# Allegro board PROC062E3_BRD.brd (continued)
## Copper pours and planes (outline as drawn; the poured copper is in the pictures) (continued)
GNDUSB on L02_GND1: 7.72,135.76 7.49,135.99 7.49,137.43 7.7,137.64 8.58,137.64 9.54,138.6 8.58,139.55 7.7,139.55 7.49,139.76 7.49,142.18 7.7,142.39 8.58,142.39 9.54,143.34 8.58,144.3 7.7,144.3 7.49,144.51 7.49,146.13 7.67,146.3 11.43,146.3 11.81,145.92 11.81,143.03 11.66,142.88 10.41,142.88 10.01,142.47 10.01,139.47 10.44,139.04 11.66,139.04 11.81,138.89 11.81,135.97 11.61,135.76
GNDUSB on L03_SIG1, L04_GND2, L05_SIG2, L08_PWR3, L11_GND4: 7.72,135.76 7.49,135.99 7.49,137.43 7.7,137.64 8.58,137.64 9.54,138.6 8.58,139.55 7.7,139.55 7.49,139.76 7.49,142.18 7.7,142.39 8.58,142.39 9.54,143.34 8.58,144.3 7.7,144.3 7.49,144.51 7.49,146.13 7.67,146.3 11.13,146.3 11.33,146.1 11.33,139.62 10.9,139.19 10.9,137.36 9.3,135.76
GNDUSB on L09_GND3: 7.72,135.76 7.49,135.99 7.49,137.43 7.7,137.64 8.58,137.64 9.54,138.6 8.58,139.55 7.7,139.55 7.49,139.76 7.49,142.18 7.7,142.39 8.58,142.39 9.54,143.34 8.58,144.3 7.7,144.3 7.49,144.51 7.49,146.13 7.67,146.3 11.13,146.3 11.33,146.1 11.33,146.08 11.33,139.62 10.9,139.19 10.9,137.36 9.3,135.76
GNDUSB on L10_SIG3: 7.72,135.76 7.49,135.99 7.49,137.43 7.7,137.64 8.58,137.64 9.54,138.6 8.58,139.55 7.7,139.55 7.49,139.76 7.49,142.18 7.7,142.39 8.58,142.39 9.54,143.34 8.58,144.3 7.7,144.3 7.49,144.51 7.49,146.13 7.67,146.3 11.13,146.3 11.33,146.1 11.33,139.62 10.9,139.19 10.9,137.36 9.3,135.76
GNDUSB on L12_SIG4: 7.72,135.76 7.49,135.99 7.49,137.43 7.7,137.64 8.58,137.64 9.54,138.6 8.58,139.55 7.7,139.55 7.49,139.76 7.49,142.18 7.7,142.39 8.58,142.39 9.54,143.34 8.58,144.3 7.7,144.3 7.49,144.51 7.49,146.13 7.67,146.3 11.13,146.3 11.33,146.1 11.33,139.62 10.9,139.19 10.9,137.37 9.29,135.76
GNDUSB on L13_GND5: 7.72,135.76 7.49,135.99 7.49,137.43 7.7,137.64 8.58,137.64 9.54,138.6 8.58,139.55 7.7,139.55 7.49,139.76 7.49,142.18 7.7,142.39 8.58,142.39 9.54,143.34 8.58,144.3 7.7,144.3 7.49,144.51 7.49,146.13 7.67,146.3 11.13,146.3 11.33,146.1 11.33,139.62 10.9,139.19 10.9,137.52 9.14,135.76
VCC1V0 on BOTTOM: 132.02,169.29 136.46,169.29 136.46,163.64 145.99,163.64 145.99,169.1 149.48,169.1 149.48,158.62 132.02,158.62
VCC1V2_DDR on BOTTOM: 165.35,153.54 165.35,159.07 168.21,159.07 168.21,165.93 170.37,165.93 170.37,166.31 174.94,166.31 174.94,153.54
VCC1V8 on TOP: 43.69,74.55 43.69,68.96 45.21,68.96 45.21,74.55
VCC1V8 on TOP: 167.39,18.8 167.39,13.34 169.1,13.34 169.1,18.8
VCC1V8 on TOP: 184.66,69.98 184.66,66.17 190.25,66.17 190.25,69.98
VCC1V8 on BOTTOM: 153.67,10.29 153.67,8.38 153.29,8 153.29,4.83 154.88,4.83 154.88,7.18 154.37,7.68 154.37,10.29
VCC1V8 on BOTTOM: 34.73,58.74 34.73,63.94 36.26,63.94 36.26,65.98 39.37,65.98 39.37,58.74
VCC1V8 on BOTTOM: 152.65,33.4 152.65,35.17 153.36,35.88 153.36,38.16 154.18,38.16 154.18,33.4
VCC1V8 on L06_PWR1: 99.59,1.03 8.01,1.03 8.01,137.12 8.58,137.12 10.06,138.6 8.58,140.07 8.01,140.07 8.01,141.87 8.58,141.87 10.06,143.34 8.58,144.82 8.01,144.82 8.01,155.94 8.6,155.94 10.06,157.39 8.6,158.84 8.01,158.84 8.01,160.69 8.6,160.69 10.06,162.14 8.6,163.59 8.01,163.59 8.01,176.77 209.16,176.77 209.16,1.03 107.3,1.03 107.3,1.6 105.82,3.08 104.34,1.6 104.34,1.03 102.55,1.03 102.55,1.6 101.07,3.08 99.59,1.6 ; 9 cut-outs
VCC1V8_CLKBUFF on L08_PWR3: 65.45,103.22 65.45,91.81 78.11,91.81 78.11,103.22
VCC3V3_IO on TOP: 136.33,64.52 136.33,53.54 137.41,53.54 137.41,64.52
VCC3V3_IO on TOP: 116.97,66.04 116.97,53.59 118.55,53.59 118.55,66.04
VCC3V3_IO on TOP: 164.53,18.86 164.53,13.21 167.07,13.21 167.07,18.86
VCC3V3_IO on TOP: 47.43,122.24 47.43,120.08 68.01,120.08 68.01,122.24
VCC3V3_IO on TOP: 143.07,147.15 143.07,151.79 143.26,151.98 145.16,151.98 145.29,151.85 145.29,149.82 144.4,149.82 144.4,147.15
VCC3V3_IO on TOP: 57.4,69.02 58.61,69.02 58.61,74.42 56.01,74.42 56.01,71.63 57.4,71.63
VCC3V3_IO on BOTTOM: 137.67,6.53 139,6.53 139,8.57 138.81,8.76 138.81,10.29 137.67,10.29
VCC3V3_IO on BOTTOM: 201.99,28.12 201.99,28.89 200.6,28.89 200.03,29.46 198.37,29.46 198.37,28.26 200.13,28.26 200.26,28.12
VCC3V3_IO on BOTTOM: 180.72,65.15 180.72,63.12 180.85,62.99 180.85,61.47 180.98,61.34 182.5,61.34 182.75,61.59 182.75,64.75 182.35,65.15
VCC3V3_IO on BOTTOM: 152.4,17.91 152.4,13.21 152.21,13.21 152.21,10.67 152.65,10.22 152.65,8.95 153.35,8.95 153.35,10.86 154.05,11.56 154.05,17.91
VCC3V3_IO on BOTTOM: 158.43,66.48 158.43,64.77 164.34,64.77 164.34,66.48
VCC3V3_IO on BOTTOM: 48.64,125.98 48.64,121.28 56.01,121.28 56.01,125.98
VCC3V3_IO on BOTTOM: 166.82,38.23 166.82,35.69 167.14,35.37 167.14,33.34 168.54,33.34 168.54,34.41 168.4,34.55 168.4,35.22 168.22,35.41 168.22,38.23
VCC3V3_IO on BOTTOM: 109.35,112.65 114.17,112.65 114.17,107.57 109.35,107.57
VCC3V3_IO on L07_PWR2: 99.59,1.03 8.01,1.03 8.01,137.12 8.58,137.12 10.06,138.6 8.58,140.07 8.01,140.07 8.01,141.87 8.58,141.87 10.06,143.34 8.58,144.82 8.01,144.82 8.01,155.94 8.6,155.94 10.06,157.39 8.6,158.84 8.01,158.84 8.01,160.69 8.6,160.69 10.06,162.14 8.6,163.59 8.01,163.59 8.01,176.77 209.16,176.77 209.16,1.03 107.3,1.03 107.3,1.6 105.82,3.08 104.34,1.6 104.34,1.03 102.55,1.03 102.55,1.6 101.07,3.08 99.59,1.6 ; 12 cut-outs
VCC3V3_PREREG on TOP: 199.71,150.88 199.71,154.24 201.04,154.24 201.04,150.88
VCC3V3_PREREG on TOP: 128.78,167.39 131.76,167.39 131.76,164.47 128.78,164.47
VCC3V3_PREREG on TOP: 29.46,76.86 31.37,76.86 31.43,76.92 32.77,76.92 32.77,77.72 33.02,77.98 33.02,79.52 29.46,79.52
VCC3V3_PREREG on TOP: 195.37,158.44 195.37,157.86 194.25,157.86 194.25,156.34 196.23,156.34 196.23,157.75 196.6,158.12 196.6,158.44
VCC3V3_PREREG on BOTTOM: 28,69.02 28,64.9 32.07,64.9 32.07,67.18 31.18,67.18 31.18,69.02
VCC3V3_PREREG on BOTTOM: 165.93,167.64 165.93,168.91 166.05,169.04 166.05,171.2 161.61,171.2 161.61,168.34 162.31,167.64
VCC3V3_PREREG on BOTTOM: 182.52,173.1 185.8,173.1 185.8,176.73 182.52,176.73
VCC3V3_PREREG on BOTTOM: 113.98,166.88 115.57,166.88 115.57,166.39 116.59,166.39 116.59,171.13 114.17,171.13 114.17,172.91 111.95,172.91 111.95,169.29 113.98,169.29
VCC3V3_PREREG on BOTTOM: 70.23,153.92 85.98,153.92 85.98,159.89 70.23,159.89
VCC3V3_PREREG on BOTTOM: 136.78,171.64 139.26,171.64 139.26,173.16 143,173.16 143,171.64 145.35,171.64 145.35,176.21 136.78,176.21
VCC3V3_PREREG on BOTTOM: 157.35,172.78 157.35,173.35 157.54,173.55 157.54,174.94 159,174.94 159,172.78
VCC3V3_PREREG on L06_PWR1: 8.13,64.77 8.13,156.55 9.57,157.39 8.13,158.23 8.13,176.78 209.17,176.78 209.17,148.53 193.75,148.53 184.28,157.99 154.43,157.99 154.43,162.94 145.92,162.94 145.92,158.5 104.65,158.5 104.65,140.65 90.42,140.65 90.42,151.13 89.79,151.76 20.47,151.76 17.91,149.2 17.91,99.19 34.54,82.55 34.54,76.58 32.64,74.68 32.64,66.67 30.73,64.77 ; 7 cut-outs
VCC3V3_XDS on TOP: 108.65,6.92 108.65,5.27 111.51,5.27 111.51,6.92
VCC3V3_XDS on L07_PWR2: 42.48,59.44 54.61,59.44 56.13,57.91 56.13,51.94 52.64,48.45 52.64,36.89 53.66,35.88 62.42,35.88 66.29,32 66.29,16.26 71.68,10.87 84.91,10.87 86.94,12.9 107.59,12.9 109.63,10.87 111.84,10.87 112.79,9.92 112.79,5.48 111.11,3.8 99.31,3.8 98.57,3.05 97.56,3.05 96.47,1.96 91.41,1.96 90.58,2.79 90.58,4.86 89.15,6.29 48.26,6.29 35.75,18.8 35.75,62.36 36.45,63.06 41.97,63.06 42.48,62.55
VCC_2V5 on TOP: 198.11,158.44 198.11,156.68 202.63,156.68 202.63,158.44
VCC_2V5 on L05_SIG2: 198.76,158.37 198.76,157.48 200.41,157.48 200.41,158.37
VCC_3V3_FT4232 on L08_PWR3: 8.19,124.33 8.19,135.19 9.31,135.19 11.3,137.19 11.3,139.04 11.73,139.47 11.73,143.36 15.43,147.07 31.75,147.07 34.49,144.33 34.49,128.64 30.18,124.33 23.19,124.33 22.89,124.64 22.89,128.27 22.2,128.96 16.76,128.96 16.1,128.3 16.1,125.12 15.32,124.33
VCC_5V0 on TOP: 15.18,143.89 15.18,142.43 18.54,142.43 18.54,143.89
VCC_5V0 on TOP: 57.4,65.66 58.93,65.66 58.93,60.9 57.4,60.9
VCC_5V0 on BOTTOM: 198.69,31.11 200.22,31.11 200.91,30.42 201.8,30.42 201.99,30.23 201.99,29.08 200.79,29.08 200.03,29.84 198.69,29.84
VCC_5V0 on BOTTOM: 168.28,48.64 168.28,41.68 166.88,41.68 166.88,44.01 166.76,44.13 166.76,45.28 164.34,45.28 164.34,48.64
VCC_5V0 on BOTTOM: 119.95,146.65 122.36,146.65 122.43,146.58 122.43,139.6 119.06,139.6 119.06,145.25 119.95,145.25
VCC_5V0 on BOTTOM: 70.87,122.17 85.98,122.17 85.98,117.35 84.96,117.35 84.96,115.32 70.87,115.32
VCC_5V0 on L06_PWR1: 198.37,30.73 198.37,29.84 200.28,29.84 200.28,30.73
VCC_5V0 on L08_PWR3: 15.05,143.51 15.05,142.37 17.02,142.37 17.02,143.51
VCC_5V0 on L08_PWR3: 57.47,62.74 57.47,60.52 58.55,60.52 58.55,62.74
VCC_5V0 on L08_PWR3: 70.87,113.22 84.55,113.22 94.04,103.73 94.04,39.35 171.2,39.35 171.2,50.96 153.54,50.96 153.54,48.96 114.87,48.96 107.31,56.52 107.31,118.11 123.38,134.18 123.38,146.43 105.79,146.43 105.79,140.21 102.36,136.78 99.06,136.78 89.15,126.87 70.87,126.87
VCC_12V0 on TOP: 78.99,163.77 78.99,153.16 84.07,153.16 84.07,154.05 94.61,154.05 94.61,163.77
VCC_12V0 on BOTTOM: 121.92,151.66 121.92,148.74 122.62,148.04 122.62,147.03 122.36,146.77 120.02,146.77 118.3,148.49 118.3,151.66
VCC_12V0 on L08_PWR3: 90.18,145.29 90.18,168.4 123.83,168.4 123.83,145.29
VDD3V3_CLKBUF on TOP: 75.18,97.79 75.69,97.79 75.69,96.77 76.96,96.77 76.96,95.5 75.18,95.5
VDD_1V0 on TOP: 45.09,65.28 45.09,63.25 42.42,63.25 42.42,65.28
VDD_1V0 on BOTTOM: 116.78,165.42 122.87,165.42 122.87,159 116.78,159
VDD_1V0 on BOTTOM: 125.16,146.65 125.16,145.22 125.09,145.16 125.09,143.28 127.38,143.28 127.38,146.33 127.06,146.65
VDD_1V0 on BOTTOM: 43.05,65.41 43.05,63.25 43.81,63.25 43.81,65.41
VDD_1V0 on L07_PWR2: 56.9,64.39 56.9,80.96 62.87,86.93 62.87,101.98 36.77,128.08 36.77,135.38 127.32,135.38 127.32,147.7 123.57,151.45 123.57,166.31 76.2,166.31 68.9,159 28.68,159 25.72,156.04 25.72,115.19 42.29,98.62 42.29,63.25 55.75,63.25
VDD_2V5 on TOP: 45.34,65.66 46.1,65.66 46.1,59.82 44.2,59.82 44.2,61.09 45.34,62.23
VDD_2V5 on TOP: 34.42,75.69 39.94,75.69 39.94,71.27 34.16,71.27 34.16,74.8 34.42,74.8
VDD_2V5 on L08_PWR3: 28.32,119.32 47.34,119.32 60.25,106.4 60.25,59.56 33.02,59.56 33.02,85.34 36.07,88.39 36.07,94.74 33.02,97.79 33.02,107.31 27.88,107.31 27.88,118.87
VDD_CORE on BOTTOM: 131.7,162.81 131.7,158.24 123.95,158.24 123.95,162.81
VDD_CORE on BOTTOM: 131.57,120.52 131.57,114.36 134.87,114.36 134.87,120.52
VDD_CORE on L07_PWR2: 124.08,163.32 124.08,151.45 127.64,147.89 127.64,103.12 137.41,93.34 152.78,93.34 153.07,93.63 153.07,105.06 142.75,115.38 142.75,160.72 140.14,163.32
VDD_DDR4 on BOTTOM: 175.77,159.32 175.77,153.61 179.9,153.61 179.9,159.32
VDD_DDR4 on L07_PWR2: 176.31,76.83 203.48,76.83 203.48,153.52 182.77,153.52 182.77,159.28 175.69,159.28 175.69,151.94 176.31,151.31 176.31,115.35 179.96,111.7 179.96,105.38 176.31,101.73
VDD_MCU on BOTTOM: 150.24,162.81 150.24,158.62 153.99,158.62 153.99,162.81
VDD_MCU on BOTTOM: 157.86,118.62 157.86,115.32 160.4,115.32 160.4,118.62
VDD_MCU on L06_PWR1: 146.69,99.57 151.26,99.57 151.64,99.95 151.64,106.55 160.02,114.94 160.02,118.75 159.77,119 156.85,119 146.18,108.33 146.18,100.08
VDD_MCU on L08_PWR3: 149.99,162.81 152.65,162.81 154.47,160.99 154.47,154.22 150.75,150.5 150.75,129.41 160.27,119.89 160.27,116.33 158.37,114.43 156.75,114.43 156.35,114.84 156.35,117.21 146.69,126.87 146.69,158.51 149.99,161.81
VDD_MMC1 on TOP: 177.08,48.99 177.08,47.33 178.1,47.33 178.18,47.24 178.18,46.48 177.93,46.23 176.4,46.23 175.9,46.74 175.9,49.28 177.17,50.55 177.17,51.82 178.69,51.82 178.69,49.28 177.36,49.28
VDD_MMC1 on BOTTOM: 179.58,57.66 182.63,57.66 182.75,57.53 182.75,56.38 182.28,55.9 182.28,50.39 182.07,50.18 177.78,50.18 177.67,50.29 177.67,52.45 177.89,52.67 179.7,52.67 179.96,52.92 179.96,55.24 179.2,56.01 179.2,57.28
VDD_MMC1_SD on TOP: 178.56,48.89 181.86,48.89 181.86,47.9 178.33,47.9 178.33,47.71 177.38,47.71 177.38,48.89 178.56,48.89
VDD_MPU on BOTTOM: 185.61,167.2 185.61,161.54 190.94,161.54 190.94,167.2
VDD_MPU on BOTTOM: 164.53,100.97 164.53,98.74 169.74,98.74 169.74,97.85 172.21,97.85 172.21,101.6 169.93,101.6 169.93,100.97
VDD_MPU on L08_PWR3: 151.32,104.52 150.62,103.82 150.62,101.79 149.29,100.46 149.29,94.74 149.67,94.36 176.41,94.36 181.7,99.65 181.7,149.89 192.98,161.16 192.98,166.94 186.23,166.94 185.29,166.01 185.29,165.16 185.36,165.1 185.36,163.26 172.21,150.11 172.21,102.87 161.86,102.87 160.21,104.52
VDDA1V8 on BOTTOM: 157.35,171.26 157.35,170.43 157.54,170.24 157.54,169.23 158.12,169.23 158.12,168.08 156.02,168.08 155.96,168.02 155.96,165.48 161.04,165.48 161.04,169.93 159.7,171.26
VDDA_1V8 on BOTTOM: 156.08,164.66 156.08,160.97 160.53,160.97 160.53,164.66
VDDA_1V8 on BOTTOM: 129.79,97.78 129.79,91.44 127.79,91.44 127.79,97.78
VDDA_1V8 on BOTTOM: 151.57,79.95 151.57,77.41 155.83,77.41 155.83,79.95
VDDA_1V8 on BOTTOM: 150.5,116.01 150.5,117.22 152.91,117.22 152.91,118.68 156.08,118.68 156.08,116.01
VDDA_1V8 on BOTTOM: 126.95,112.86 126.95,111.86 129.79,111.86 129.79,114.3 129.54,114.55 129.54,117.09 127.46,119.17 123.04,119.17 123.04,114.54 125.37,114.54 125.84,115.01 127.05,115.01 127.24,114.82 127.24,113.16
VDDA_1V8 on L08_PWR3: 160.34,164.72 160.34,160.4 159.23,159.29 157.07,159.29 153.29,163.07 148.08,163.07 145.54,160.53 145.54,126.49 151.83,120.21 154.11,120.21 155.96,118.36 155.96,112.9 155.45,112.39 145.03,112.39 145.03,108.1 140.95,104.01 133.35,104.01 130.28,107.09 115.95,107.09 115.95,97.92 129.67,97.92 129.67,91.57 115.95,91.57 115.95,81.41 116.2,81.15 156.21,81.15 156.21,73.47 113.47,73.47 108.08,78.87 108.08,116.59 137.28,145.79 137.28,158.22 147.36,168.3 152.5,168.3 156.08,164.72
VDDR_VTT on TOP: 195.26,135.19 195.26,143.45 197.1,145.29 197.1,148.27 185.55,148.27 185.55,149.85 195.58,149.85 195.58,150.43 200.66,150.43 200.66,149.1 198.5,149.1 198.5,144.78 196.98,143.26 196.98,135.19
VDDR_VTT on BOTTOM: 185.55,149.87 185.55,148.34 197.23,148.34 197.23,149.87
VDDR_VTT on BOTTOM: 195.26,143.45 195.26,134.36 196.98,134.36 196.98,143.45
VIN on TOP: 43.05,155.57 43.05,143.08 58.99,143.08 58.99,155.57
VINPUT on TOP: 30.23,129.72 30.23,150.71 42.67,150.71 42.67,143.13 46.49,143.13 46.49,129.72
(no net) on TOP: outline of 83 points within 7.51,0.52 209.66,177.28 ; 100 cut-outs
(no net) on BOTTOM: 7.51,0.52 7.51,135.08 7.81,135.38 11.84,135.38 12.09,135.64 12.09,136.3 12.32,136.53 14.22,136.53 14.48,136.78 14.48,138.15 14.1,138.53 12.19,138.53 12.09,138.43 12.09,138.3 11.86,138.07 11.38,138.07 11.28,138.18 11.28,139.01 11.73,139.47 11.73,142.14 12.09,142.49 12.83,142.49 12.93,142.6 12.93,144.27 12.67,144.53 12.04,144.53 11.79,144.78 11.79,146.76 11.56,146.99 7.86,146.99 7.51,147.35 7.51,151.78 7.65,151.92 9.12,151.92 9.96,151.08 17.5,151.08 17.78,151.36 17.78,155.78 17.42,156.13 12.85,156.13 12.47,156.51 12.47,157.94 11.23,159.18 11.23,160.45 12.5,161.72 13.13,161.72 13.54,162.13 13.54,165.2 13.08,165.66 13.08,166.73 12.57,167.23 7.66,167.23 7.51,167.39 7.51,177.28 209.66,177.28 209.66,0.52 109,0.52 108.81,0.71 108.81,2.54 107.24,4.11 107.24,5 107.04,5.21 105.13,5.21 104.98,5.05 104.98,3.56 104.85,3.43 102.01,3.43 101.9,3.53 101.9,5.11 101.8,5.21 99.82,5.21 99.69,5.08 99.69,3.86 98.88,3.05 97.79,3.05 97.21,2.46 97.21,0.85 96.88,0.52 ; 107 cut-outs
(no net) on L03_SIG1: 130.94,0.51 106.98,0.51 106.77,0.71 106.77,1.6 105.82,2.56 104.86,1.6 104.86,0.71 104.65,0.51 102.23,0.51 102.02,0.72 102.02,1.6 101.07,2.56 100.11,1.6 100.11,0.71 99.9,0.51 7.49,0.51 7.49,26.42 7.5,153.76 7.65,153.9 8.97,153.9 10.95,155.88 11.96,155.88 12.24,156.16 12.24,157.89 11.94,158.19 10.49,158.19 10.39,158.29 10.39,161.09 10.57,161.26 12.27,161.26 12.67,161.67 12.67,165.2 12.22,165.66 7.81,165.66 7.5,165.96 7.51,177.28 209.66,177.28 209.68,27.43 209.68,0.51 147.45,0.51 ; 158 cut-outs
(no net) on L05_SIG2: 7.51,139.57 7.51,142.37 8.58,142.37 9.56,143.34 8.58,144.32 7.51,144.32 7.51,153.77 7.76,154.03 9.09,154.03 10.95,155.88 11.96,155.88 12.24,156.16 12.24,157.96 12.01,158.19 10.54,158.19 10.39,158.34 10.39,161.06 10.57,161.24 12.24,161.24 12.67,161.67 12.67,165.2 12.22,165.66 7.77,165.66 7.51,165.93 7.51,177.28 209.66,177.28 209.66,0.52 106.79,0.52 106.79,1.6 105.82,2.57 104.85,1.6 104.85,0.72 104.65,0.52 102.23,0.52 102.04,0.72 102.04,1.6 101.07,2.57 100.1,1.6 100.1,0.52 7.51,0.52 7.51,137.62 8.58,137.62 9.56,138.6 8.58,139.57 ; 192 cut-outs
(no net) on L10_SIG3: 7.51,139.57 7.51,142.37 8.58,142.37 9.56,143.34 8.58,144.32 7.51,144.32 7.51,156.45 8.6,156.45 9.55,157.39 8.6,158.34 7.51,158.34 7.51,161.2 8.6,161.2 9.55,162.14 8.6,163.09 7.51,163.09 7.51,177.28 209.66,177.28 209.66,0.52 106.79,0.52 106.79,1.6 105.82,2.57 104.85,1.6 104.85,0.72 104.65,0.52 102.22,0.52 102.04,0.71 102.04,1.6 101.07,2.57 100.1,1.6 100.1,0.52 7.51,0.52 7.51,137.62 8.58,137.62 9.56,138.6 8.58,139.57 ; 182 cut-outs
(no net) on L12_SIG4: 7.51,139.57 7.51,142.37 8.58,142.37 9.56,143.34 8.58,144.32 7.51,144.32 7.51,156.45 8.6,156.45 9.55,157.39 8.6,158.34 7.51,158.34 7.51,161.2 8.6,161.2 9.55,162.14 8.6,163.09 7.51,163.09 7.51,177.28 209.66,177.28 209.66,0.52 106.79,0.52 106.79,1.6 105.82,2.57 104.85,1.6 104.85,0.72 104.65,0.52 102.23,0.52 102.04,0.72 102.04,1.6 101.07,2.57 100.1,1.6 100.1,0.52 7.51,0.52 7.51,137.62 8.58,137.62 9.56,138.6 8.58,139.57 ; 155 cut-outs
CS on TOP: 85.85,139.95 95,139.95 95,135.25 85.85,135.25
DDR_VPP on TOP: 193.1,147.83 193.1,145.73 194.75,145.73 194.75,147.83
DDR_VPP on L08_PWR3: 197.31,147.07 197.31,78.42 181.55,78.42 181.55,81.2 185.42,81.2 185.42,91.5 182.5,91.5 182.5,94.7 185.42,94.7 185.42,106.17 182.05,106.17 182.05,108.5 185.42,108.5 185.42,119.89 182.05,119.89 182.05,122.36 185.42,122.36 185.42,133.22 182.36,133.22 182.36,136.18 185.42,136.18 185.42,147.07
FT4232_USB_VBUS on BOTTOM: 11.18,137.59 11.18,136.97 13.91,136.97 14.1,137.16 14.1,137.92 13.92,138.1 13.49,138.1 13.26,137.87 12.27,137.87 12.01,137.62 11.2,137.62
HS on TOP: 84.65,135 95.5,135 95.5,140.34 92.84,140.34 92.84,144.85 101.73,144.85 101.73,129.03 84.65,129.03
HS_L on TOP: 101.47,146.05 94.36,146.05 94.36,146.94 86.36,146.94 86.36,154.05 86.61,154.31 101.47,154.31
MAIN on TOP: 29.59,173.48 29.59,156.08 59.08,156.08 59.08,173.48
MCU_EARTH on TOP, L02_GND1, L03_SIG1, L04_GND2, L05_SIG2, L08_PWR3, L09_GND3, L10_SIG3, L11_GND4, L12_SIG4: 16.94,128.57 22.02,128.57 22.48,128.12 22.48,119.81 21.59,118.92 21.59,113.56 22.48,112.67 22.48,108.94 22.23,108.69 20.65,108.69 20.27,109.07 17.48,109.07 17.12,109.42 17.12,110.26 16.64,110.74 16.64,113.23 16.48,113.39 16.48,128.12
MCU_EARTH on BOTTOM, L13_GND5: 16.94,128.57 22.02,128.57 22.48,128.12 22.48,119.81 21.59,118.92 21.59,113.56 22.48,112.67 22.48,108.94 22.22,108.68 20.65,108.68 20.27,109.06 17.49,109.06 17.12,109.42 17.12,110.26 16.64,110.74 16.64,113.23 16.48,113.39 16.48,128.12
PRG_EARTH on L04_GND2: 8,78.61 8,104.78 34.93,104.78 34.93,78.61 ; 4 cut-outs
SHIELD on BOTTOM: 24.64,174.62 24.64,168.28 45.09,168.28 45.09,174.62
SOC_DVDD1V8 on TOP: 184.66,74.93 184.66,70.74 189.48,70.74 189.48,74.93
SOC_DVDD1V8 on BOTTOM: 169.16,91.58 169.16,89.92 170.31,89.92 170.56,89.66 172.1,89.66 172.45,90.02 172.45,95.63 172.33,95.76 171.28,95.76 171.16,95.63 171.16,94.44 171.02,94.3 169.39,94.3 169.23,94.13 169.23,91.64
SOC_DVDD1V8 on L08_PWR3: 140.34,99.57 146.06,99.57 146.06,106.28 146.83,107.06 150.11,107.06 150.11,101.47 149.1,100.46 149.1,94.49 149.48,94.11 179.2,94.11 179.2,77.22 179.71,76.71 187.71,76.71 189.61,74.8 189.61,70.87 188.72,69.98 173.48,69.98 169.93,73.53 169.93,86.74 144.4,86.74 140.34,90.81
SOC_DVDD3V3 on BOTTOM: 115.19,112.71 115.19,107.57 119.13,107.57 119.13,112.71
SOC_DVDD3V3 on BOTTOM: 125.88,105.66 125.88,99.8 127.38,98.3 131.44,98.3 131.44,99.44 131.29,99.59 130.35,99.59 130.2,99.44 128.91,99.44 128.91,101.92 129.73,101.92 129.73,104.67 129.98,104.93 129.98,105.78 129.83,105.93 129.07,105.93 128.8,105.66
SOC_DVDD3V3 on L06_PWR1: 145.73,107.51 147.83,105.41 147.83,98.93 148.08,98.68 152.78,98.68 154.69,96.77 154.69,94.11 154.31,93.73 150.37,93.73 150.24,93.6 150.24,88.14 145.92,88.14 141.35,92.71 139.95,92.71 139.95,101.73
SOC_DVDD3V3 on L08_PWR3: 129.38,103.42 142.2,103.42 142.2,105.28 145.64,105.28 145.9,105.02 145.9,100.88 145.06,100.04 142.12,100.04 140.89,101.26 135.09,101.26 131.94,98.11 118.02,98.11 114.98,101.14 114.98,112.86 119.94,112.86
SOC_MPU on BOTTOM: 176.91,171.7 182.18,171.7 182.18,170.31 182.5,169.99 182.5,167 184.72,167 184.72,161.48 176.91,161.48
SOC_VDDS_DDR on BOTTOM: 164.6,158.05 164.6,153.48 160.4,153.48 160.4,158.05
SOC_VDDS_DDR on BOTTOM: 164.53,107.44 164.53,103.82 171.45,103.82 171.45,109.63 168.96,109.63 168.96,107.44
SOC_VDDS_DDR on L06_PWR1: 160.15,157.73 160.15,152.53 172.97,152.53 172.97,129.92 166.5,123.44 157.23,123.44 155.32,121.54 155.32,112.38 157.22,110.48 168.92,110.48 169.74,109.66 169.74,107.51 170.05,107.19 173.61,107.19 174.62,108.2 179.71,108.2 180.98,109.47 180.98,143 185.04,147.07 193.29,147.07 194.31,148.08 184.66,157.73
SOC_VDDS_DDR on L07_PWR2: 153.29,105.41 160.4,105.41 164.72,109.73 171.2,109.73 171.58,109.35 171.58,106.3 171.2,105.92 168.66,105.92 167.64,104.9 167.64,100.84 163.7,96.9 154.31,96.9 153.29,97.92
USB1_SHIELD on TOP: 7.67,154.41 7.52,154.56 7.52,156.46 8.6,156.46 9.54,157.39 8.6,158.32 7.52,158.32 7.52,161.21 8.6,161.21 9.54,162.14 8.6,163.07 7.52,163.07 7.52,165 7.85,165.33 11.91,165.33 12.37,164.87 12.37,161.85 12.01,161.49 10.39,161.49 10.11,161.21 10.11,158.32 10.46,157.96 11.89,157.96 12.01,157.84 12.01,156.26 11.81,156.06 10.82,156.06 9.17,154.41
USB1_SHIELD on BOTTOM: 7.65,155.09 7.52,155.22 7.52,156.46 8.6,156.46 9.54,157.39 8.6,158.32 7.52,158.32 7.52,161.21 8.6,161.21 9.54,162.14 8.6,163.07 7.52,163.07 7.52,166.47 7.85,166.8 12.27,166.8 12.45,166.62 12.45,165.38 12.17,165.1 12.17,161.95 11.71,161.49 10.39,161.49 10.11,161.21 10.11,158.32 10.34,158.09 11.79,158.09 12.01,157.86 12.01,156.46 11.66,156.11 9.73,156.11 9.63,156.01 9.63,155.5 9.22,155.09
USB1_SHIELD on L02_GND1, L03_SIG1, L04_GND2, L05_SIG2, L06_PWR1, L07_PWR2, L08_PWR3, L09_GND3, L10_SIG3, L11_GND4, L12_SIG4, L13_GND5: 7.67,154.41 7.52,154.56 7.52,156.46 8.6,156.46 9.54,157.39 8.6,158.32 7.52,158.32 7.52,161.21 8.6,161.21 9.54,162.14 8.6,163.07 7.52,163.07 7.52,165 7.85,165.33 11.91,165.33 12.37,164.87 12.37,161.75 12.12,161.49 10.39,161.49 10.11,161.21 10.11,158.32 10.46,157.96 11.89,157.96 12.07,157.78 12.07,156.31 11.81,156.06 10.82,156.06 9.17,154.41
USB1_VBUS on TOP: 14.61,151.96 14.61,156.36 14.3,156.67 13.08,156.67 12.88,156.46 12.47,156.46 12.4,156.54 12.4,158.01 12.12,158.29 12.12,158.69 12.18,158.75 13.72,158.75 14.54,157.92 15.23,157.92 15.39,157.76 16,157.76 16.26,157.51 16.26,156.24 15.95,155.93 15.95,155.24 16,155.19 16,153.67 17.72,153.67 17.72,151.96
VMAIN on TOP: 75.56,137.67 75.56,129.86 80.9,129.86 80.9,137.67
VMAIN on TOP: 53.78,134.17 53.78,137.99 47.08,137.99 47.08,142.56 66.29,142.56 66.29,134.17
VMAIN on BOTTOM: 75.06,129.79 79.25,129.79 79.25,135 84.58,135 84.58,131.44 89.28,131.44 89.28,142.49 85.09,142.49 85.09,138.7 75.06,138.7
VMAIN on BOTTOM: 47.75,129.67 47.75,141.86 66.29,141.86 66.29,134.24 53.78,134.24 53.78,131.06 48.64,131.06 48.64,129.67
VMAIN on L07_PWR2: 61.48,141.93 79.79,141.93 79.79,129.65 74.3,129.65 74.3,134.28 61.48,134.28
VMAIN on L08_PWR3: 61.48,142.29 79.79,142.29 79.79,129.65 74.3,129.65 74.3,134.28 61.48,134.28
VPP_1V8 on TOP: 129.16,170.18 131.89,170.18 131.89,173.74 129.16,173.74
VPP_1V8 on BOTTOM: 146.24,116.01 146.24,117.6 147.57,117.6 147.57,116.01
VPP_1V8 on L08_PWR3: 129.25,174.24 129.25,170.28 133.89,170.28 133.89,174.24
XDS_SHIELD on TOP: 97.6,0.81 97.6,2.31 97.96,2.67 99.06,2.67 100.08,3.68 100.08,4.65 100.23,4.8 101.73,4.8 101.73,3.05 105.16,3.05 105.16,4.8 106.68,4.8 106.81,4.67 106.81,3.94 108.43,2.31 108.43,0.89 108.18,0.64 106.93,0.64 106.81,0.76 106.81,2.29 106.43,2.67 105.41,2.67 104.78,2.03 104.78,0.64 102.11,0.64 102.11,2.16 101.6,2.67 100.58,2.67 100.08,2.16 100.08,0.68 99.93,0.53 97.88,0.53
XDS_SHIELD on BOTTOM, L02_GND1, L03_SIG1, L04_GND2, L05_SIG2, L06_PWR1, L07_PWR2, L08_PWR3, L09_GND3, L10_SIG3, L11_GND4, L12_SIG4, L13_GND5: 97.84,0.51 97.66,0.69 97.66,2.31 98.02,2.67 99.06,2.67 100.08,3.68 100.08,4.65 100.23,4.8 101.35,4.8 101.52,4.62 101.52,3.35 101.83,3.05 105.03,3.05 105.36,3.38 105.36,4.65 105.51,4.8 106.68,4.8 106.81,4.67 106.81,3.94 108.43,2.31 108.43,0.64 108.31,0.51 106.98,0.51 106.77,0.71 106.77,1.6 105.82,2.56 104.86,1.6 104.86,0.71 104.65,0.51 102.23,0.51 102.02,0.71 102.02,1.6 101.07,2.56 100.11,1.6 100.11,0.71 99.9,0.51
XDS_USB_VBUS on TOP: 104.35,7.11 104.35,6.6 104.78,6.6 104.78,5.46 108.33,5.46 108.33,7.11
N17781485 on BOTTOM: 31.94,64.14 31.94,60.01 33.72,60.01 33.72,64.14
N17781689 on BOTTOM: 162.56,160.72 165.35,160.72 165.35,163.77 164.78,164.34 164.78,166.56 162.56,166.56
N17781734 on BOTTOM: 177.23,174.94 177.23,172.47 182.05,172.47 182.05,174.94
N17782154 on BOTTOM: 132.4,171.83 132.4,170.43 136.27,170.43 136.27,171.83
N17782156 on BOTTOM: 145.8,172.02 145.8,170.31 149.67,170.31 149.67,172.02
N17785477 on BOTTOM: 49.15,130.68 56.01,130.68 56.01,128.52 49.15,128.52
N17785579 on BOTTOM: 114.49,164.66 114.49,163.26 114.24,163 114.24,159 115.95,159 115.95,162.94 115.7,163.19 115.7,164.66
N17786037 on TOP: 33.65,78 39.75,78 39.75,80.1 34.16,80.1 33.65,79.59
N17839730 on BOTTOM: 9.91,151.57 9.91,154.81 10.67,155.57 17.08,155.57 17.08,151.57
N18546005 on TOP: 59.56,164.47 59.56,146.43 67.31,146.43 67.31,164.47
N18968753 on TOP: 15.75,148.34 17.78,148.34 17.78,146.56 18.73,146.56 18.73,145.1 15.75,145.1
N19753729 on BOTTOM: 81.28,130.18 81.28,127.25 99.06,127.25 99.06,131.19 84.71,131.19 84.71,130.18
N19753760 on BOTTOM: 86.61,123.95 86.61,117.6 87.38,117.6 87.38,116.4 99.38,116.4 99.38,123.95
N19754201 on BOTTOM: 81.15,147.45 81.15,143 99.25,143 99.25,147.45
N19754522 on BOTTOM: 86.74,158.62 86.74,150.56 99.5,150.56 99.5,158.62

Small or netless copper shapes (teardrops, artwork), in the pictures only: 2448 on TOP, 1510 on BOTTOM, 515 on L03_SIG1, 607 on L05_SIG2, 27 on L06_PWR1, 11 on L07_PWR2, 19 on L08_PWR3, 405 on L10_SIG3, 499 on L12_SIG4

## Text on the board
Ref Des/Assembly Bottom: D | C | B | A | BASY CP CARD REV E3
Ref Des/Silkscreen Bottom: DGND | VDD_2V5 | VPP_1V8 | EXT | PORz | INT | VCC1V0 | SoC_AVDD1V8 | VDDA1V8 | VCC1V2_DDR | SOC_MPU | VDD_MPU | VCC1V8 | SoC_DVDD3V3 | VDD_1V0 | VDD_CORE | VDD_MCU | SoC_VDDS_DDR | SOC_SAFETY_ERRORZ | VDD_DDR | MIPI | DISPLAY | NOT FCC APPROVED FOR RESALE | FOR EVALUATION ONLY;
User.Comments: BOARD NAME: | AM654x EVM PROCESSOR BOARD | REV: E3 | DATE: 02/07/2018 | DESCRIPTION: | SHEET | OF | 21 | PROC062 | SCALE: 1 | CR_ETHERNET_1 | TEXAS INSTRUMENTS
Ref Des/Assembly Top: TASY CP CARD REV E3
Ref Des/Silkscreen Top: VINPUT | B | VCC_12V0 | VCC3V3_PREREG | VCC3V3_IO | VCC_5V0 | A | DGND | I2C1_SCL | I2C1_SDA | SoC_DVDD1V8 | VCC_2V5 | USB2 Port 1 | VMAIN | MIPI | cTI | 1V8 | 3V3 | MCU_SDA | MCU_SCL | VDDR_VTT | ETHERNET | MCU | XDS110_USB | PORz | JTAG_MUX_SEL | MCU_BOOTMODE | BOOTMODE SW | WARM_RST | CSI LVL | MCU_PUSH BUTTON | ADC | Expansion Card | 1.8V max | Serdes | TIMER | SPI1 | UART | PRU2 | ETH0/ETH1 | 12V-24V 5A MAX | JTAG | WKUP UART0 | SD CARD | OFF | 12V-24V | CSI2 CAMERA | ON | APPLICATION CARD | MCU UART1 | PCB #:3P0014 | PCB REV:E3 | AM654x EVM PROCESSOR BOARD | PROC062 | ASSM #:4P0081 REV:1.0
PAGE_OUTLINE: LAYOUT BY | REVIEWED BY | APPROVED BY | SIGNATURES | AMB | UAK | ZA | DATE | 030918 | SIZE | SCALE: | D | NONE | SHEET 1 OF 21 | PROC062 | Rev | E3 | TEXAS INSTRUMENTS | AM654x EVM PROCESSOR BOARD
DISPLAY_TOP: 1 | 2 | S/N
User.7: 15. | 16. | ALL UNCONNECTED VIA'S SHALL BE SUPPRESSED IN INTERNAL LAYERS. | PCB SHALL BE MANUFACTURED USING I-SPEED OR EQUIVALENT WITH Er 3.34. | ALL THE IMPEDANCE SHALL BE MATCHED AS PER IMPEDANCE TABLE WITH +/-10% TOLERANCE. | DIA WITH 40MIL DRILL HAS A DUPLICATE HOLE AT ONE OF THE LOCATION, THIS SHALL BE IGNORED DURING FABRICATION. | AND QUANTITY CAN BE CONSIDERED AS 11 HOLES. | VIA HOLES THAT HAVE MASK OPEN SHALL BE FILLED WITH NON CONDUCTIVE INK AND CAP PLATED, | DETAIL-A
User.22: GROUND-PLANE-05 | 16
User.25: INNER-SIGNAL-04 | 15
User.38: 02 | 03 | 04 | 05 | 06 | 07 | 08 | 10 | 11 | 12 | STRIPLINE | EDGE COUPLED STRIPLINE | MICROSTRIP | EDGE COUPLED MICROSTRIP | L5 | L3 | L3,L5 | L10,L12 | L1 | L1,L14 | 3.0 | 4.3 | 3.3 | 4.2 | 4.1 | 6.2 | 10.5 | 5.2 | 8.2 | 3.5 | 7.9 | 4.4 | NA | 7.4 | 5.3 | 5.0 | 100 | 80 | 50 | 90 | 85 | 40 | L2/L4,L4/L6 | L9/L11,L11/L13 | L11/L13 | L4/L6 | L2/L4 | L2,L13 | L4
User.39: 1.45oz
User.42: FIGURE | SIZE | 8.0 | 24.0 | 32.0 | 36.0 | 40.0 | 44.0 | 46.0 | 66.0 | 86.0 | 34.0 | 42.0 | 56.0 | 68.0 | 88.0 | 108.0 | 126.0 | 52.0x24.0 | 64.0x32.0 | 86.0x24.0 | 98.0x24.0 | 120.0x30.0 | 140.0x40.0 | DRILL CHART: TOP to BOTTOM | ALL UNITS ARE IN MILS | TOLERANCE | +3.0/-4.0 | +3.0/-3.0 | +2.0/-2.0 | PLATED | NON-PLATED | QTY | 4718 | 10 | 2 | 5 | 38 | 34 | 63 | 18 | 6 | 8 | 12 | 3 | 4 | 14 | 1
User.43: ASSEMBLY NOTES:- | 1 - All MSL components should be baked as per JEDEC standard. | 2 - PCB should be baked at 120 degree for 8 hours. | 3 - Board assembly must comply with workmanship standards IPC-A-610 Class 2, unless otherwise specified. | 7 - The assembled board are wrapped in ESD Covers(individual) and packed securely before shipment. | 4 - These assemblies are ESD sensitive, ESD precautions shall be observed. | 6 - Provide serial numbers to the assembled boards for identification. | 5 - These assemblies must be clean and free from flux and all contaminants. Use of no clean flux is not acceptable. | PROC062(001) E3 ASSEMBLY TOP
User.44: 5 - These assemblies must be clean and free from flux and all contaminants. Use of no clean flux is not acceptable. | 6 - Provide serial numbers to the assembled boards for identification. | 4 - These assemblies are ESD sensitive, ESD precautions shall be observed. | 3 - Board assembly must comply with workmanship standards IPC-A-610 Class 2, unless otherwise specified. | 7 - The assembled board are wrapped in ESD Covers(individual) and packed securely before shipment. | 1 - All MSL components should be baked as per JEDEC standard. | 2 - PCB should be baked at 120 degree for 8 hours. | ASSEMBLY NOTES:- | PROC062(001) E3 ASSEMBLY BOTTOM
User.45: ASSEMBLY NOTES:- | 1 - All MSL components should be baked as per JEDEC standard. | 2 - PCB should be baked at 120 degree for 8 hours. | 3 - Board assembly must comply with workmanship standards IPC-A-610 Class 2, unless otherwise specified. | 7 - The assembled board are wrapped in ESD Covers(individual) and packed securely before shipment. | 4 - These assemblies are ESD sensitive, ESD precautions shall be observed. | 6 - Provide serial numbers to the assembled boards for identification. | 5 - These assemblies must be clean and free from flux and all contaminants. Use of no clean flux is not acceptable. | PROC062(003) E3 ASSEMBLY BOTTOM | PROC062(002) E3 ASSEMBLY BOTTOM | PROC062(005) E3 ASSEMBLY BOTTOM | PROC062(004) E3 ASSEMBLY BOTTOM | PROC062(004) E3 ASSEMBLY TOP | PROC062(002) E3 ASSEMBLY TOP | PROC062(005) E3 ASSEMBLY TOP | PROC062(003) E3 ASSEMBLY TOP
